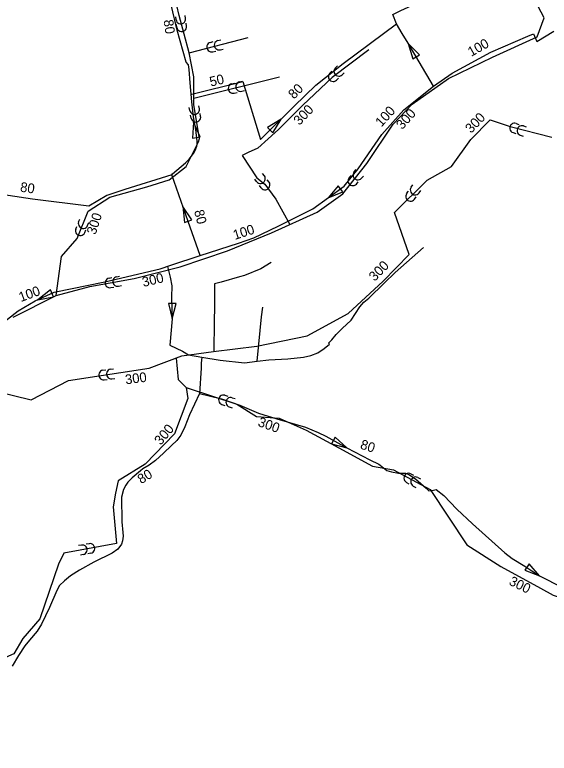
# Model space of a CAD drawing. Extents: x -438814 to -433781, y -1130090 to -1121339.
# Drawn here: x -438249 to -437697, y -1124704 to -1123942 of the extents above; entities that cross this region are included whole.
import ezdxf

# ---------------------------------------------------------------- set-up
doc = ezdxf.new("R2010")
doc.units = 0
for name, color, linetype in [('Vrstva 11', 7, 'Continuous'), ('Vrstva 12', 7, 'Continuous'), ('Vrstva 13', 7, 'Continuous'), ('Vrstva 14', 7, 'Continuous'), ('Vrstva 19', 7, 'Continuous'), ('Vrstva 34', 7, 'Continuous'), ('Vrstva 36', 7, 'Continuous'), ('Vrstva 38', 7, 'Continuous'), ('Vrstva 39', 7, 'Continuous'), ('Vrstva 48', 7, 'Continuous'), ('Vrstva 49', 7, 'Continuous')]:
    doc.layers.add(name, color=color, linetype=linetype)

msp = doc.modelspace()

# ---------------------------------------------------------------- linework, layer by layer
at = {"layer": 'Vrstva 11'}
for points in [[(-437816.67, -1124015.51), (-437843.02, -1123971.22), (-437848.99, -1123961.23), (-437855.1, -1123951.11), (-437858.9, -1123941.65), (-437850.68, -1123937.63), (-437819.41, -1123923.19), (-437816.05, -1123921.08), (-437813.8, -1123919.28), (-437807.29, -1123909.97), (-437802.45, -1123903.55), (-437797.77, -1123899.23), (-437791.38, -1123891.73), (-437788.91, -1123888.02), (-437782.11, -1123880.44), (-437778.7, -1123875.29), (-437761.64, -1123857.22), (-437739.28, -1123842.8), (-437731.18, -1123836.89)], [(-438058, -1124190.31), (-438070.16, -1124155.5), (-438087.24, -1124107.32), (-438086.44, -1124106.1), (-438072.92, -1124094.63), (-438069.1, -1124090.82), (-438064.83, -1124085.11), (-438062.92, -1124082.2), (-438061.29, -1124077.49), (-438061.11, -1124075.95), (-438060.93, -1124072.24), (-438062.31, -1124060.18), (-438064.65, -1124047.22), (-438066.42, -1124031.61), (-438068.25, -1124012.19), (-438069.38, -1123998.53), (-438069.97, -1123993.51), (-438072.3, -1123990.72), (-438081.69, -1123957.74), (-438087.49, -1123933.04)], [(-438273.08, -1124268.41), (-438245.92, -1124247.58), (-438228.49, -1124237.39), (-438208.62, -1124228.37), (-438156.33, -1124217.5), (-438099.2, -1124204.35), (-438088.33, -1124200.5), (-438058, -1124190.31), (-438018.23, -1124177.73), (-438002.39, -1124172.29), (-437977.26, -1124160), (-437941.31, -1124142.43), (-437908.99, -1124118.91), (-437894.51, -1124101.02), (-437870.09, -1124065.56), (-437847.45, -1124040.2), (-437816.67, -1124015.51), (-437797.52, -1124002.24), (-437757.45, -1123980.5), (-437719.2, -1123963.97), (-437713.54, -1123961.48), (-437709.92, -1123969.63), (-437692.49, -1123958.76)], [(-438056.1, -1124295.56), (-438037.27, -1124298.43), (-438012.19, -1124301.4), (-437998.96, -1124299.6), (-437986.92, -1124298.19), (-437967.31, -1124297.11), (-437951.14, -1124295.43), (-437943.49, -1124293.54), (-437936.41, -1124290.84), (-437929.57, -1124286.43), (-437924.3, -1124282.06), (-437925.21, -1124280.83), (-437921.92, -1124277.66), (-437917.23, -1124272.16), (-437911.16, -1124265.93), (-437901.73, -1124257.09), (-437892.77, -1124243.39), (-437888.65, -1124238.47), (-437883.41, -1124234.37), (-437867.76, -1124218.9), (-437856.45, -1124208.15), (-437826.93, -1124182.3)], [(-438091.71, -1124201.7), (-438088.75, -1124212.68), (-438087.02, -1124221.72), (-438087.4, -1124233.4), (-438086.64, -1124255.9), (-438089.12, -1124282.93), (-438076.01, -1124289.32), (-438069.9, -1124292.91), (-438056.1, -1124295.56), (-438056.75, -1124301.69), (-438056.86, -1124306.7), (-438058.44, -1124332.96), (-438068.97, -1124354.89), (-438073.59, -1124367.22), (-438077.68, -1124376.1), (-438082.12, -1124381.42), (-438087.34, -1124386.78), (-438095.62, -1124394.49), (-438104.07, -1124402.01), (-438110.49, -1124406.82), (-438117.13, -1124410.57), (-438119.65, -1124412.76), (-438128.07, -1124419.86), (-438132.52, -1124424.61), (-438134.57, -1124427.5), (-438137.05, -1124431.97), (-438139.08, -1124439.89), (-438138.97, -1124465.29), (-438137.68, -1124476.33), (-438137.4, -1124480.09), (-438137.97, -1124485.02), (-438139.25, -1124488.56), (-438142.82, -1124493.84), (-438148.95, -1124497.84), (-438167.89, -1124507.2), (-438182.58, -1124515.4), (-438191.97, -1124521.24), (-438198.19, -1124526.25), (-438203.22, -1124531.3), (-438206.11, -1124536.33), (-438213.59, -1124553.79), (-438221.72, -1124570.97), (-438226.22, -1124578.39), (-438234.17, -1124587.5), (-438239.05, -1124593.55), (-438245.72, -1124603.41), (-438251.96, -1124614.54)], [(-437998.96, -1124299.6), (-437994.55, -1124253.83), (-437993.19, -1124243.76)], [(-438058.42, -1124332.9), (-438035.97, -1124338.5), (-438016.72, -1124345.03), (-437997.66, -1124353.29), (-437978.66, -1124359.24), (-437949.07, -1124367.86), (-437936.06, -1124373.27), (-437927.89, -1124377.09), (-437906.16, -1124389.08), (-437882.67, -1124401.38), (-437873.26, -1124405.86), (-437871.83, -1124406.88), (-437864.93, -1124412.45), (-437860.33, -1124413.8), (-437852.86, -1124415.04), (-437845.77, -1124415.36), (-437842.27, -1124416.75), (-437835.43, -1124421.09), (-437824.32, -1124430.57), (-437821.68, -1124433.36), (-437816.87, -1124432.68), (-437814.07, -1124432.14), (-437806.1, -1124438.28), (-437792.74, -1124452.46), (-437776.62, -1124467.48), (-437743.21, -1124497.62), (-437735.33, -1124503.48), (-437722.25, -1124511.37), (-437715.16, -1124516.07), (-437707.1, -1124521.34), (-437658.93, -1124545.77)]]:
    msp.add_lwpolyline(points, dxfattribs=at)
at = {"layer": 'Vrstva 12'}
for points in [[(-437838.16, -1123987.22), (-437831.28, -1123983.13), (-437842.9, -1123971.42)], [(-438065.69, -1124069.23), (-438057.82, -1124067.76), (-438064.7, -1124052.76)], [(-437910.39, -1124124.88), (-437915.1, -1124118.41), (-437925.68, -1124131.05)], [(-438074.1, -1124156.38), (-438066.56, -1124153.71), (-438075.67, -1124139.96)], [(-438209.35, -1124233.09), (-438212.66, -1124225.81), (-438225.57, -1124236.06)], [(-438082.62, -1124239.9), (-438090.62, -1124239.89), (-438086.64, -1124255.9)], [(-437918.3, -1124377.92), (-437922.13, -1124384.94), (-437906.16, -1124389.08)], [(-437717.98, -1124508.95), (-437722.53, -1124515.53), (-437707.1, -1124521.34)]]:
    msp.add_lwpolyline(points, close=True, dxfattribs=at)
at = {"layer": 'Vrstva 13'}
for points in [[(-438087.24, -1124107.32), (-438135.67, -1124122.18), (-438154.23, -1124128.52), (-438172.8, -1124139.61), (-438230.97, -1124132.14), (-438288.66, -1124123.51), (-438311.91, -1124072.81), (-438319.59, -1124056.35), (-438327.96, -1124045.25), (-438339.96, -1124041.86), (-438377.03, -1124037.56), (-438409.62, -1124038.24), (-438422.48, -1124035.55), (-438448.29, -1124026.95), (-438457.11, -1124021.74), (-438470.02, -1124006.12), (-438477.01, -1123997.55), (-438486.06, -1123973.09), (-438488.31, -1123960.72), (-438482.88, -1123887.58), (-438483.1, -1123883.34)], [(-438067.71, -1124024.2), (-438013.72, -1124010.95), (-437995.41, -1124070.83), (-437960.69, -1124036.31), (-437938.4, -1124014.48), (-437910.1, -1123992.06), (-437855.1, -1123951.11)]]:
    msp.add_lwpolyline(points, dxfattribs=at)
at = {"layer": 'Vrstva 14'}
msp.add_lwpolyline([(-437988.43, -1124058.25), (-437982.79, -1124063.92), (-437974.26, -1124049.8)], close=True, dxfattribs=at)
at = {"layer": 'Vrstva 34'}
for points in [[(-438206.56, -1124231.61), (-438201.28, -1124191.53), (-438184.84, -1124172.87), (-438173.73, -1124144.59), (-438151.32, -1124130.33), (-438113.07, -1124119.46), (-438089.8, -1124112.47), (-438072.38, -1124098.43), (-438059.48, -1124073.07), (-438058.59, -1124069.54), (-438064.47, -1124034.9), (-438064.47, -1124028.14), (-438064.47, -1124005.92), (-438069.22, -1123981.31), (-438079.39, -1123942.68), (-438084.32, -1123921.69), (-438091.7, -1123888.17), (-438094.43, -1123853.74), (-438089.88, -1123814.16), (-438077.15, -1123781.61)], [(-438250.99, -1124254.05), (-438206.56, -1124231.61), (-438171.83, -1124222.58), (-438126.04, -1124214.21), (-438078.48, -1124202.29), (-438029.53, -1124185.73), (-437984.09, -1124167.17), (-437936.95, -1124145.64), (-437910.59, -1124126.83), (-437885.82, -1124095.5), (-437858.51, -1124054.75), (-437838.91, -1124034.03), (-437801.18, -1124007.78), (-437755.63, -1123985.55), (-437709.64, -1123964.52), (-437702.46, -1123945.06), (-437714.57, -1123921.97)], [(-438308.92, -1124317.08), (-438270.78, -1124330.05), (-438232.63, -1124339.64), (-438193.93, -1124319.41), (-438110.46, -1124306.7), (-438076.83, -1124294.13), (-438044.07, -1124289.63), (-437999.41, -1124284.16), (-437947.43, -1124273.24), (-437905, -1124250.33), (-437868.85, -1124217.12), (-437841.76, -1124189.51), (-437857.04, -1124146.16), (-437823.32, -1124112.77), (-437798.27, -1124098.47), (-437778.05, -1124070.78), (-437758.37, -1124050.48), (-437737.69, -1124057.16), (-437694.33, -1124068.4)], [(-437984.46, -1124197.68), (-437995.2, -1124204.3), (-438011.96, -1124211.16), (-438017.06, -1124212.34), (-438036.32, -1124217.86), (-438043.08, -1124219.74), (-438043.02, -1124242.99), (-438043.32, -1124258.67), (-438043.79, -1124289.52)]]:
    msp.add_lwpolyline(points, dxfattribs=at)
at = {"layer": 'Vrstva 36'}
for p, q in [((-438069.22, -1123981.31), (-438008.43, -1123965.42)), ((-438064.47, -1124028.14), (-437976.04, -1124005.88))]:
    msp.add_line(p, q, dxfattribs=at)
for points in [[(-437883.72, -1123978.01), (-437921.52, -1124006.77), (-437951.85, -1124035.08), (-437976.98, -1124060.44), (-437998.43, -1124079.62), (-438008.39, -1124084.15), (-438014.51, -1124087.26), (-437999.35, -1124110.13), (-437991.2, -1124116.92), (-437979.65, -1124132.32), (-437965.28, -1124158.58)], [(-438082.71, -1124296.33), (-438080.68, -1124318.45), (-438072.31, -1124326.82), (-438020.02, -1124344.04), (-437999.49, -1124356.71), (-437976.17, -1124358.29), (-437948.33, -1124370.75), (-437914.61, -1124389.09), (-437879.85, -1124408.04), (-437858.12, -1124411.89), (-437820.32, -1124432.05), (-437782.35, -1124489.03), (-437747.04, -1124511.45), (-437706.34, -1124534.06), (-437693.21, -1124541.3), (-437638.95, -1124558.7), (-437608.88, -1124582.22), (-437594.16, -1124601.01), (-437514.82, -1124685.5), (-437504.62, -1124699.09), (-437468.4, -1124757.51)], [(-438072.31, -1124326.82), (-438070.72, -1124338.14), (-438084.53, -1124374.6), (-438114.66, -1124405.79), (-438142.73, -1124423), (-438145.44, -1124435.91), (-438147.89, -1124449.85), (-438144.26, -1124487.89), (-438198.59, -1124497.85), (-438204.18, -1124509.07), (-438223.42, -1124565.68), (-438241.08, -1124586.06), (-438250.36, -1124601.69), (-438274.72, -1124612.47), (-438316.37, -1124626.51), (-438356.89, -1124637.15), (-438399.67, -1124651.19), (-438459.74, -1124674)]]:
    msp.add_lwpolyline(points, dxfattribs=at)
at = {"layer": 'Vrstva 38'}
for p, q in [((-438082.8, -1123946.98), (-438083.17, -1123944)), ((-438072.87, -1123945.75), (-438073.24, -1123942.77)), ((-438081.82, -1123954.92), (-438082.18, -1123951.94)), ((-438071.89, -1123953.69), (-438072.26, -1123950.71)), ((-438068.57, -1124040.6), (-438069.08, -1124037.64)), ((-438058.72, -1124038.92), (-438059.22, -1124035.96)), ((-438067.23, -1124048.48), (-438067.74, -1124045.53)), ((-438057.38, -1124046.81), (-438057.88, -1124043.85)), ((-437731.32, -1124054.08), (-437728.49, -1124055.06)), ((-437723.77, -1124056.7), (-437720.93, -1124057.69)), ((-437734.61, -1124063.52), (-437731.77, -1124064.51)), ((-437727.05, -1124066.15), (-437724.22, -1124067.13)), ((-437903.94, -1124110.04), (-437901.96, -1124107.78)), ((-437898.66, -1124104.02), (-437896.68, -1124101.77)), ((-437896.42, -1124116.63), (-437894.44, -1124114.38)), ((-437891.14, -1124110.62), (-437889.16, -1124108.37)), ((-437839.8, -1124120.04), (-437838.04, -1124117.61)), ((-437844.49, -1124126.52), (-437842.73, -1124124.09)), ((-437836.39, -1124132.39), (-437834.63, -1124129.96)), ((-437831.7, -1124125.91), (-437829.94, -1124123.48)), ((-438183.45, -1124155.69), (-438182.35, -1124152.9)), ((-438186.36, -1124163.14), (-438185.27, -1124160.34)), ((-438174.14, -1124159.34), (-438173.04, -1124156.54)), ((-438177.05, -1124166.79), (-438175.96, -1124163.99)), ((-438151.96, -1124213.81), (-438149.01, -1124213.25)), ((-438144.1, -1124212.33), (-438141.15, -1124211.77)), ((-438142.24, -1124222.15), (-438139.29, -1124221.59)), ((-438150.1, -1124223.64), (-438147.16, -1124223.08)), ((-438158.39, -1124308.9), (-438155.42, -1124308.49)), ((-438150.46, -1124307.82), (-438147.49, -1124307.41)), ((-438157.04, -1124318.81), (-438154.06, -1124318.4)), ((-438149.11, -1124317.73), (-438146.14, -1124317.32))]:
    msp.add_line(p, q, dxfattribs=at)
for centre, start, end in [((-438077.84, -1123946.36), 187.05501, 7.05608), ((-438076.85, -1123954.3), 187.05501, 7.05608), ((-438063.64, -1124039.76), 189.64057, 9.64164), ((-438062.3, -1124047.65), 189.64057, 9.64164), ((-437732.96, -1124058.8), 70.83676, 250.83783), ((-437725.41, -1124061.43), 70.83676, 250.83783), ((-437894.9, -1124107.32), 138.73555, 318.73662), ((-437900.18, -1124113.34), 138.73555, 318.73662), ((-437835.75, -1124122.98), 144.06903, 324.07011), ((-437840.44, -1124129.45), 144.06903, 324.07011), ((-438178.79, -1124157.51), 158.60056, 338.60163), ((-438181.71, -1124164.96), 158.60056, 338.60163), ((-438151.03, -1124218.72), 100.69894, 280.70001), ((-438143.17, -1124217.24), 100.69894, 280.70001), ((-438157.71, -1124313.85), 97.76326, 277.76433), ((-438149.79, -1124312.77), 97.76326, 277.76433)]:
    msp.add_arc(centre, 5, start, end, dxfattribs=at)
at = {"layer": 'Vrstva 39'}
for p, q in [((-438047.28, -1123970.41), (-438044.37, -1123969.65)), ((-438039.54, -1123968.38), (-438036.63, -1123967.62)), ((-438037.01, -1123978.06), (-438034.1, -1123977.3)), ((-438044.75, -1123980.08), (-438041.84, -1123979.32)), ((-437923.84, -1124002.1), (-437921.65, -1124000.06)), ((-437918, -1123996.65), (-437915.8, -1123994.6)), ((-437917.02, -1124009.41), (-437914.83, -1124007.37)), ((-437911.17, -1124003.96), (-437908.98, -1124001.91)), ((-438025.13, -1124013.08), (-438022.22, -1124012.35)), ((-438017.37, -1124011.13), (-438014.46, -1124010.4)), ((-438022.69, -1124022.78), (-438019.78, -1124022.05)), ((-438014.93, -1124020.82), (-438012.02, -1124020.09)), ((-437991.49, -1124108.2), (-437993.29, -1124105.79)), ((-437999.49, -1124114.19), (-438001.29, -1124111.79)), ((-437986.69, -1124114.6), (-437988.49, -1124112.2)), ((-437994.69, -1124120.59), (-437996.49, -1124118.19)), ((-438032.27, -1124334.79), (-438029.42, -1124335.72)), ((-438024.66, -1124337.27), (-438021.81, -1124338.2)), ((-438035.37, -1124344.3), (-438032.51, -1124345.23)), ((-438027.76, -1124346.78), (-438024.91, -1124347.71)), ((-437840.02, -1124415.88), (-437837.37, -1124417.29)), ((-437832.96, -1124419.64), (-437830.32, -1124421.05)), ((-437844.73, -1124424.7), (-437842.08, -1124426.11)), ((-437837.67, -1124428.46), (-437835.02, -1124429.88)), ((-438172.66, -1124488.02), (-438175.61, -1124488.56)), ((-438180.53, -1124489.46), (-438183.48, -1124490)), ((-438178.72, -1124499.29), (-438181.67, -1124499.84)), ((-438170.85, -1124497.85), (-438173.81, -1124498.39))]:
    msp.add_line(p, q, dxfattribs=at)
for centre, start, end in [((-438046.01, -1123975.24), 104.64999, 284.65106), ((-438038.27, -1123973.22), 104.64999, 284.65106), ((-437914.58, -1124000.3), 133.02116, 313.02223), ((-437920.43, -1124005.76), 133.02116, 313.02223), ((-438023.91, -1124017.93), 104.12707, 284.12814), ((-438016.15, -1124015.98), 104.12707, 284.12814), ((-437995.49, -1124111.19), 216.85739, 36.85847), ((-437990.69, -1124117.6), 216.85739, 36.85847), ((-438033.82, -1124339.54), 71.95871, 251.95978), ((-438026.21, -1124342.02), 71.95871, 251.95978), ((-437842.37, -1124420.29), 61.93578, 241.93685), ((-437835.31, -1124424.05), 61.93578, 241.93685), ((-438171.76, -1124492.93), 280.39253, 100.3936), ((-438179.63, -1124494.38), 280.39253, 100.3936)]:
    msp.add_arc(centre, 5, start, end, dxfattribs=at)

# ---------------------------------------------------------------- texts
at = {"layer": 'Vrstva 19'}
for s, rotation, p in [('80', 278.32115, (-438095.75, -1123947.56)), ('100', 29.41726, (-437777.84, -1123985.44)), ('50', 13.60783, (-438046.81, -1124016.12)), ('80', 44.96567, (-437960.97, -1124029.56)), ('100', 47.588, (-437870.57, -1124058.28)), ('80', 351.80772, (-438244.32, -1124124.41)), ('80', 284.02465, (-438064.15, -1124144.49)), ('100', 17.93979, (-438022.04, -1124174.38)), ('100', 20.1542, (-438243.13, -1124238.57)), ('80', 342.46214, (-437893.2, -1124389.69)), ('80', 31.85068, (-438118.76, -1124426.72))]:
    msp.add_text(s, height=10, rotation=rotation, dxfattribs=at).set_placement(p)
at = {"layer": 'Vrstva 48'}
for rotation, p in [(46.10648, (-437777.91, -1124064.87)), (72.14363, (-438165.98, -1124169.62)), (45.5533, (-437877.56, -1124217.7)), (13.37194, (-438116.53, -1124222.98)), (7.33277, (-438134.75, -1124323.54))]:
    msp.add_text('300', height=10, rotation=rotation, dxfattribs=at).set_placement(p)
at = {"layer": 'Vrstva 49'}
for rotation, p in [(46.14802, (-437955.31, -1124056.67)), (48.52967, (-437849.01, -1124061.02)), (340.5168, (-437998.95, -1124366.34)), (49.82827, (-438098.62, -1124386.94)), (334.17653, (-437739.56, -1124530.05))]:
    msp.add_text('300', height=10, rotation=rotation, dxfattribs=at).set_placement(p)

doc.saveas('drawing.dxf')
